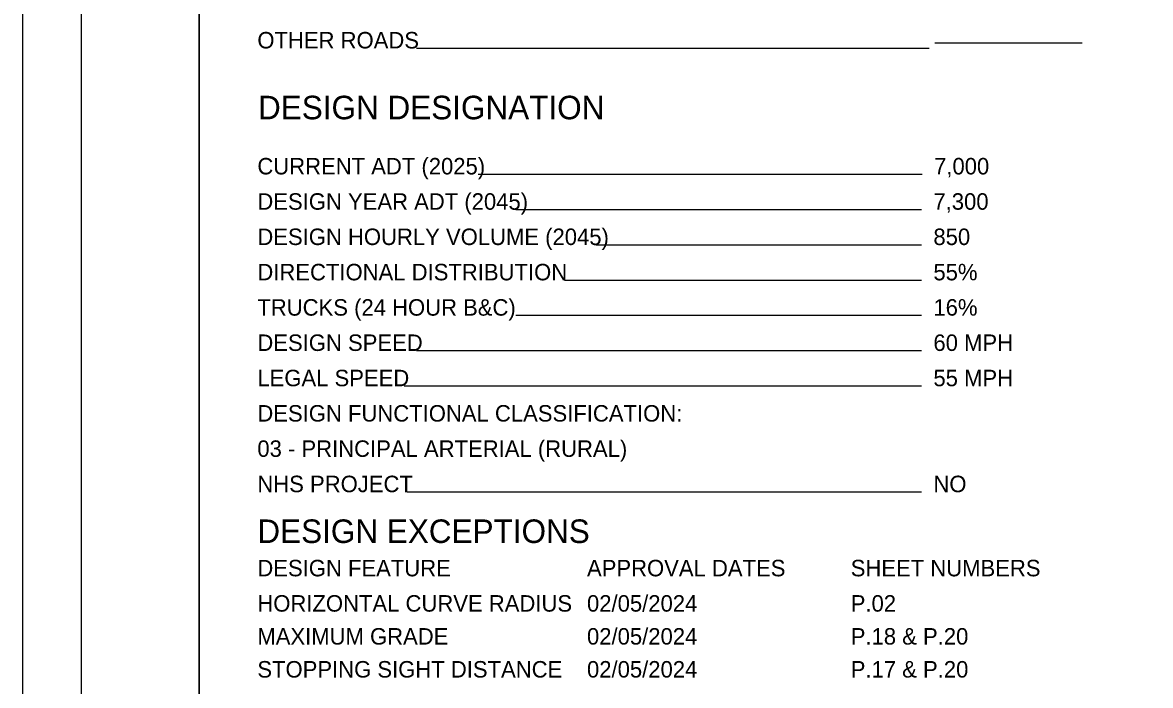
# Model space of a CAD drawing. Extents: x 0 to 34, y 0 to 22.
# Drawn here: x 0 to 9.58, y 5.46 to 11.1 of the extents above; entities that cross this region are included whole.
import ezdxf

# ---------------------------------------------------------------- set-up
doc = ezdxf.new("R2010")
doc.units = 0
for name, color, linetype in [('SH_Border', 7, 'Continuous'), ('SH_Cut_Line', 7, 'Continuous'), ('SH_Data', 7, 'Continuous'), ('SH_Text', 7, 'Continuous')]:
    doc.layers.add(name, color=color, linetype=linetype)

msp = doc.modelspace()

# ---------------------------------------------------------------- linework, layer by layer
at = {"layer": 'SH_Border'}
for points in [[(0.5, 21.5), (1.5, 21.5), (1.5, 0.5), (0.5, 0.5)], [(1.5, 21.5), (33.5, 21.5), (33.5, 0.5), (1.5, 0.5)]]:
    msp.add_lwpolyline(points, close=True, dxfattribs=at)
at = {"layer": 'SH_Cut_Line'}
msp.add_lwpolyline([(0, 0), (34, 0), (34, 22), (0, 22)], close=True, dxfattribs=at)
at = {"layer": 'SH_Data'}
for p, q in [((9, 10.9223), (7.75, 10.9223)), ((7.7, 10.8767), (3.3471, 10.8767)), ((7.6424, 9.8062), (3.871, 9.8062)), ((7.6368, 9.5062), (4.1885, 9.5062)), ((7.6368, 9.2062), (4.8723, 9.2062)), ((7.6368, 8.9062), (4.6037, 8.9062)), ((7.6368, 8.6062), (4.1885, 8.6062)), ((7.6368, 8.3062), (3.346, 8.3062)), ((7.6368, 8.0062), (3.2422, 8.0062)), ((7.6368, 7.1062), (3.2669, 7.1062))]:
    msp.add_line(p, q, dxfattribs=at)

# ---------------------------------------------------------------- texts
msp.add_text('DESIGN DESIGNATION', height=0.2, dxfattribs=at).set_placement((2, 10.2747))
at = {"layer": 'SH_Text'}
for s, height, p in [('OTHER ROADS', 0.14, (1.9944, 10.8767)), ('CURRENT ADT (2025)', 0.14, (1.9944, 9.8062)), ('7,000', 0.14, (7.7424, 9.8062)), ('DESIGN YEAR ADT (2045)', 0.14, (1.9944, 9.5062)), ('7,300', 0.14, (7.7368, 9.5062)), ('DESIGN HOURLY VOLUME (2045)', 0.14, (1.9944, 9.2062)), ('850', 0.14, (7.7368, 9.2062)), ('DIRECTIONAL DISTRIBUTION', 0.14, (1.9944, 8.9062)), ('55%', 0.14, (7.7368, 8.9062)), ('TRUCKS (24 HOUR B&C)', 0.14, (1.9944, 8.6062)), ('16%', 0.14, (7.7368, 8.6062)), ('DESIGN SPEED', 0.14, (1.9944, 8.3062)), ('60 MPH', 0.14, (7.7368, 8.3062)), ('LEGAL SPEED', 0.14, (1.9944, 8.0062)), ('55 MPH', 0.14, (7.7368, 8.0062)), ('DESIGN FUNCTIONAL CLASSIFICATION:', 0.14, (1.9944, 7.7062)), ('03 - PRINCIPAL ARTERIAL (RURAL)', 0.14, (1.9944, 7.4062)), ('NHS PROJECT', 0.14, (1.9944, 7.1062)), ('NO', 0.14, (7.7368, 7.1062)), ('DESIGN EXCEPTIONS', 0.2, (1.9944, 6.6744)), ('DESIGN FEATURE', 0.14, (1.9944, 6.3911)), ('APPROVAL DATES', 0.14, (4.7944, 6.3911)), ('SHEET NUMBERS', 0.14, (7.0344, 6.3911)), ('HORIZONTAL CURVE RADIUS', 0.14, (1.9944, 6.0911)), ('02/05/2024', 0.14, (4.7944, 6.0911)), ('P.02', 0.14, (7.0344, 6.0911)), ('MAXIMUM GRADE', 0.14, (1.9944, 5.8111)), ('02/05/2024', 0.14, (4.7944, 5.8111)), ('P.18 & P.20', 0.14, (7.0344, 5.8111)), ('STOPPING SIGHT DISTANCE', 0.14, (1.9944, 5.5311)), ('02/05/2024', 0.14, (4.7944, 5.5311)), ('P.17 & P.20', 0.14, (7.0344, 5.5311))]:
    msp.add_text(s, height=height, dxfattribs=at).set_placement(p)

doc.saveas('drawing.dxf')
